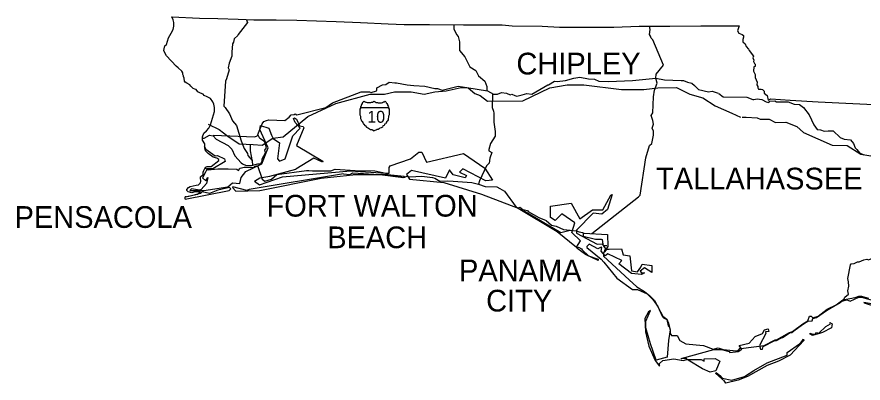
# Model space of a CAD drawing. Extents: x -820.2 to -798.1, y -2199.1 to -2182.2.
# Drawn here: x -808.86 to -807.105, y -2183.81 to -2183.051 of the extents above; entities that cross this region are included whole.
import ezdxf

# ---------------------------------------------------------------- set-up
doc = ezdxf.new("R2010")
doc.units = 0
for name, color, linetype in [('FLMap1', 7, 'Continuous'), ('FLMap2', 7, 'Continuous'), ('FLMap3', 7, 'Continuous'), ('TextMisc', 7, 'Continuous')]:
    doc.layers.add(name, color=color, linetype=linetype)

msp = doc.modelspace()

# ---------------------------------------------------------------- linework, layer by layer
at = {"layer": 'FLMap1'}
msp.add_line((-808.1473, -2183.2389), (-808.0888, -2183.2389), dxfattribs=at)
for points in [[(-808.119, -2183.226), (-808.12, -2183.227), (-808.121, -2183.227), (-808.1225, -2183.2285), (-808.1235, -2183.2285), (-808.125, -2183.2285), (-808.126, -2183.2295), (-808.127, -2183.2295), (-808.1285, -2183.2295), (-808.1295, -2183.2295), (-808.1319, -2183.2295), (-808.1329, -2183.2295), (-808.1344, -2183.2285), (-808.1354, -2183.2285), (-808.1379, -2183.227), (-808.1389, -2183.227), (-808.1404, -2183.226), (-808.1414, -2183.227), (-808.1424, -2183.2285), (-808.1439, -2183.2295), (-808.1439, -2183.2309), (-808.1448, -2183.2329), (-808.1458, -2183.2344), (-808.1458, -2183.2364), (-808.1473, -2183.2379), (-808.1473, -2183.2404), (-808.1483, -2183.2423), (-808.1483, -2183.2448), (-808.1483, -2183.2473), (-808.1483, -2183.2498), (-808.1483, -2183.2518), (-808.1483, -2183.2543), (-808.1473, -2183.2567), (-808.1473, -2183.2592), (-808.1473, -2183.2617), (-808.1458, -2183.2642), (-808.1448, -2183.2667), (-808.1439, -2183.2677), (-808.1424, -2183.2701), (-808.1414, -2183.2726), (-808.1404, -2183.2736), (-808.1379, -2183.2761), (-808.1364, -2183.2771), (-808.1344, -2183.2796), (-808.1319, -2183.281), (-808.1305, -2183.282), (-808.1285, -2183.283), (-808.126, -2183.2845), (-808.1235, -2183.2845), (-808.1225, -2183.2855), (-808.119, -2183.287)], [(-808.119, -2183.226), (-808.1176, -2183.227), (-808.1166, -2183.227), (-808.1156, -2183.2285), (-808.1141, -2183.2285), (-808.1116, -2183.2285), (-808.1106, -2183.2295), (-808.1096, -2183.2295), (-808.1081, -2183.2295), (-808.1071, -2183.2295), (-808.1052, -2183.2295), (-808.1032, -2183.2295), (-808.1017, -2183.2285), (-808.1007, -2183.2285), (-808.0997, -2183.227), (-808.0972, -2183.227), (-808.0957, -2183.226), (-808.0947, -2183.227), (-808.0937, -2183.2285), (-808.0937, -2183.2295), (-808.0923, -2183.2309), (-808.0913, -2183.2329), (-808.0913, -2183.2344), (-808.0898, -2183.2364), (-808.0888, -2183.2379), (-808.0888, -2183.2404), (-808.0878, -2183.2423), (-808.0878, -2183.2448), (-808.0878, -2183.2473), (-808.0878, -2183.2498), (-808.0878, -2183.2518), (-808.0878, -2183.2543), (-808.0888, -2183.2567), (-808.0888, -2183.2592), (-808.0898, -2183.2617), (-808.0898, -2183.2642), (-808.0913, -2183.2667), (-808.0923, -2183.2677), (-808.0937, -2183.2701), (-808.0947, -2183.2726), (-808.0972, -2183.2736), (-808.0982, -2183.2761), (-808.1007, -2183.2771), (-808.1017, -2183.2796), (-808.1042, -2183.281), (-808.1071, -2183.282), (-808.1081, -2183.283), (-808.1106, -2183.2845), (-808.1131, -2183.2845), (-808.1141, -2183.2855), (-808.119, -2183.287)]]:
    msp.add_lwpolyline(points, dxfattribs=at)
at = {"layer": 'FLMap2'}
for points in [[(-808.5105, -2183.4289), (-808.5105, -2183.4244), (-808.5011, -2183.4219), (-808.4951, -2183.4205), (-808.4852, -2183.4185), (-808.4817, -2183.416), (-808.4792, -2183.4135), (-808.4906, -2183.4135), (-808.4966, -2183.416), (-808.5045, -2183.4135), (-808.507, -2183.411), (-808.507, -2183.409), (-808.5035, -2183.4046), (-808.5001, -2183.4026), (-808.4877, -2183.4001), (-808.4832, -2183.3991), (-808.4792, -2183.3952), (-808.4782, -2183.3917), (-808.4792, -2183.3847), (-808.4792, -2183.3823), (-808.4733, -2183.3778), (-808.4733, -2183.3728), (-808.4723, -2183.3694), (-808.4688, -2183.3624), (-808.4653, -2183.3609), (-808.4619, -2183.3609), (-808.4569, -2183.3609), (-808.441, -2183.3485), (-808.441, -2183.3465), (-808.445, -2183.3441), (-808.4524, -2183.3416), (-808.4629, -2183.3346), (-808.4688, -2183.3287), (-808.4698, -2183.3227), (-808.4698, -2183.3178), (-808.4698, -2183.3143), (-808.4748, -2183.3068), (-808.4748, -2183.2999), (-808.4723, -2183.2925), (-808.4663, -2183.287), (-808.4619, -2183.282), (-808.4584, -2183.2751), (-808.45, -2183.2473), (-808.45, -2183.2389), (-808.451, -2183.2319), (-808.4534, -2183.227), (-808.4584, -2183.22), (-808.4653, -2183.2166), (-808.4713, -2183.2141), (-808.4733, -2183.2111), (-808.4792, -2183.2091), (-808.4842, -2183.2066), (-808.4877, -2183.2017), (-808.4906, -2183.2007), (-808.4941, -2183.1997), (-808.4991, -2183.1947), (-808.5011, -2183.1922), (-808.507, -2183.1888), (-808.5105, -2183.1863), (-808.512, -2183.1843), (-808.513, -2183.1783), (-808.5145, -2183.1749), (-808.5145, -2183.1734), (-808.5155, -2183.1709), (-808.5155, -2183.1674), (-808.5179, -2183.1635), (-808.5249, -2183.1565), (-808.5293, -2183.153), (-808.5492, -2183.1317), (-808.5527, -2183.1258), (-808.5551, -2183.1208), (-808.5537, -2183.1143), (-808.5527, -2183.1109), (-808.5492, -2183.1084), (-808.5452, -2183.0945), (-808.5398, -2183.0851), (-808.5353, -2183.0776), (-808.5343, -2183.0707), (-808.5343, -2183.0632), (-808.5353, -2183.0573), (-808.5383, -2183.0513)], [(-808.384, -2183.0563), (-808.3815, -2183.0632), (-808.4008, -2183.0876), (-808.4018, -2183.0895), (-808.4093, -2183.097), (-808.4103, -2183.1039), (-808.4128, -2183.1074), (-808.4137, -2183.1243), (-808.4137, -2183.1292), (-808.4137, -2183.1327), (-808.4197, -2183.1471), (-808.4212, -2183.1565), (-808.4197, -2183.161), (-808.4247, -2183.1793), (-808.4271, -2183.1843), (-808.4306, -2183.2364), (-808.4281, -2183.2389), (-808.4187, -2183.2518), (-808.4128, -2183.2667), (-808.4043, -2183.2761), (-808.3949, -2183.3078), (-808.3884, -2183.3237), (-808.3815, -2183.3346), (-808.3805, -2183.3381), (-808.3721, -2183.3485), (-808.3711, -2183.3589)], [(-807.9538, -2183.0677), (-807.9538, -2183.0757), (-807.9479, -2183.0876), (-807.9444, -2183.092), (-807.9419, -2183.1029), (-807.9419, -2183.1208), (-807.931, -2183.1337), (-807.9206, -2183.155), (-807.9082, -2183.1625), (-807.9022, -2183.1734), (-807.8893, -2183.1843), (-807.8849, -2183.1957), (-807.8849, -2183.2041)], [(-807.6671, -2183.5003), (-807.5703, -2183.4244), (-807.5669, -2183.4205), (-807.555, -2183.3431), (-807.5475, -2183.3178), (-807.543, -2183.3133), (-807.5396, -2183.2964), (-807.5396, -2183.288), (-807.5421, -2183.282), (-807.5396, -2183.2736), (-807.5406, -2183.2657), (-807.544, -2183.2557), (-807.5406, -2183.2498), (-807.5396, -2183.2166), (-807.5371, -2183.2032), (-807.5321, -2183.1888), (-807.5346, -2183.1783), (-807.5336, -2183.1699), (-807.5187, -2183.1516), (-807.5406, -2183.099), (-807.544, -2183.0955), (-807.5455, -2183.091), (-807.5475, -2183.0876), (-807.5465, -2183.0776), (-807.5475, -2183.0697)], [(-808.0362, -2183.1937), (-808.0139, -2183.1947), (-807.993, -2183.1997), (-807.9876, -2183.1997), (-807.9777, -2183.2032), (-807.9444, -2183.1947), (-807.9266, -2183.1972), (-807.8834, -2183.2041), (-807.8715, -2183.2111), (-807.863, -2183.2111), (-807.8546, -2183.2076), (-807.8442, -2183.2091), (-807.8368, -2183.2126), (-807.8333, -2183.2111), (-807.8273, -2183.2141), (-807.8229, -2183.2156), (-807.8174, -2183.2141), (-807.8115, -2183.2126), (-807.802, -2183.2101), (-807.7916, -2183.2111), (-807.7589, -2183.1922), (-807.7569, -2183.1922), (-807.745, -2183.1843), (-807.739, -2183.1853), (-807.7221, -2183.1828), (-807.7043, -2183.1783), (-807.6924, -2183.1759), (-807.6745, -2183.1793), (-807.6621, -2183.1803), (-807.6527, -2183.1843), (-807.6328, -2183.1853), (-807.5827, -2183.1828), (-807.5346, -2183.1783), (-807.5168, -2183.1818), (-807.482, -2183.1828), (-807.4771, -2183.1828), (-807.4686, -2183.1863), (-807.4602, -2183.1888), (-807.4547, -2183.1937), (-807.4463, -2183.2017), (-807.4255, -2183.2066), (-807.4175, -2183.2051), (-807.4056, -2183.2091)], [(-808.4758, -2183.3024), (-808.4713, -2183.3024), (-808.4604, -2183.2964), (-808.4524, -2183.2974), (-808.4465, -2183.3044), (-808.4212, -2183.3178), (-808.4137, -2183.3252), (-808.4078, -2183.3391), (-808.3949, -2183.3535), (-808.3919, -2183.356), (-808.384, -2183.3589), (-808.3731, -2183.3589), (-808.3602, -2183.356), (-808.3542, -2183.356), (-808.3532, -2183.3545), (-808.3507, -2183.351), (-808.3507, -2183.345), (-808.3507, -2183.345), (-808.3443, -2183.3331), (-808.3453, -2183.3277), (-808.3443, -2183.3252), (-808.3418, -2183.3227), (-808.3453, -2183.3108), (-808.3483, -2183.3078), (-808.3557, -2183.3034), (-808.3602, -2183.2949), (-808.3507, -2183.2726), (-808.3473, -2183.2677), (-808.3418, -2183.2657), (-808.3373, -2183.2642), (-808.3041, -2183.2657), (-808.2952, -2183.2592), (-808.2907, -2183.2543), (-808.2848, -2183.2533), (-808.2823, -2183.2518), (-808.2788, -2183.2543), (-808.2193, -2183.2389), (-808.2049, -2183.2295), (-808.1458, -2183.2066), (-808.1285, -2183.2066), (-808.125, -2183.2076), (-808.1141, -2183.2041), (-808.1131, -2183.2032), (-808.1131, -2183.1982), (-808.1017, -2183.1922), (-808.0947, -2183.1912), (-808.0878, -2183.1863), (-808.0759, -2183.1878), (-808.0724, -2183.1878), (-808.0506, -2183.1922), (-808.0362, -2183.1937)], [(-807.873, -2183.2111), (-807.874, -2183.2389), (-807.8715, -2183.2463), (-807.8705, -2183.2508), (-807.8705, -2183.2691), (-807.868, -2183.289), (-807.868, -2183.2984), (-807.8774, -2183.3133), (-807.8809, -2183.3262), (-807.8809, -2183.3287), (-807.875, -2183.3321), (-807.8789, -2183.3441), (-807.8799, -2183.3545), (-807.8859, -2183.3599), (-807.9003, -2183.3907), (-807.9022, -2183.3976)], [(-807.4041, -2183.2101), (-807.3947, -2183.2166), (-807.3461, -2183.2175), (-807.3337, -2183.2225), (-807.3312, -2183.2225), (-807.3243, -2183.221), (-807.3148, -2183.2225), (-807.3054, -2183.227), (-807.3004, -2183.2285), (-807.298, -2183.226), (-807.288, -2183.225), (-807.2846, -2183.227), (-807.2727, -2183.227), (-807.2598, -2183.227), (-807.2479, -2183.2319), (-807.2369, -2183.2329), (-807.2285, -2183.2389), (-807.2166, -2183.2543), (-807.2072, -2183.2751), (-807.2002, -2183.2845), (-807.1928, -2183.2855), (-807.1853, -2183.288), (-807.1774, -2183.287), (-807.1665, -2183.287), (-807.1526, -2183.3009), (-807.1437, -2183.3044), (-807.1308, -2183.3059), (-807.1248, -2183.3133), (-807.1213, -2183.3227), (-807.1179, -2183.3262), (-807.1119, -2183.3331), (-807.1035, -2183.3371)], [(-808.3031, -2183.345), (-808.2872, -2183.2974), (-808.2719, -2183.282), (-808.2823, -2183.2701), (-808.2857, -2183.2617), (-808.2838, -2183.2602), (-808.2798, -2183.2632), (-808.2738, -2183.2771), (-808.2659, -2183.2786), (-808.2644, -2183.281), (-808.2798, -2183.3178)], [(-808.3517, -2183.356), (-808.3383, -2183.3227), (-808.3557, -2183.2845), (-808.3542, -2183.2761), (-808.3373, -2183.282), (-808.3314, -2183.2964), (-808.3279, -2183.3034), (-808.315, -2183.3123), (-808.3195, -2183.345), (-808.315, -2183.35), (-808.3031, -2183.345)], [(-808.4524, -2183.2964), (-808.3661, -2183.2999), (-808.3612, -2183.2974), (-808.3602, -2183.2964)], [(-808.4713, -2183.3192), (-808.4678, -2183.3252), (-808.4485, -2183.3391), (-808.444, -2183.3381), (-808.4291, -2183.345), (-808.4281, -2183.351), (-808.4534, -2183.3659), (-808.4653, -2183.3659), (-808.4688, -2183.3728), (-808.4748, -2183.3847), (-808.4678, -2183.3907), (-808.4639, -2183.3837), (-808.4663, -2183.3966), (-808.4772, -2183.409), (-808.4807, -2183.41), (-808.4976, -2183.4076), (-808.5011, -2183.411), (-808.4723, -2183.411), (-808.4222, -2183.4036), (-808.4128, -2183.3952), (-808.3974, -2183.3966), (-808.3949, -2183.3837), (-808.385, -2183.3718), (-808.3517, -2183.356)], [(-808.2798, -2183.3178), (-808.2252, -2183.35), (-808.2262, -2183.3525), (-808.2441, -2183.3441), (-808.2813, -2183.3669)], [(-808.1677, -2183.3703), (-808.0947, -2183.3753), (-808.0878, -2183.3753), (-808.0878, -2183.3634), (-808.0853, -2183.3599), (-808.0436, -2183.345), (-808.0258, -2183.3312), (-808.0198, -2183.3312), (-808.0104, -2183.3525), (-807.9335, -2183.3346), (-807.8893, -2183.3644), (-807.873, -2183.3892), (-807.8869, -2183.3907), (-807.935, -2183.3659), (-807.9419, -2183.3728), (-807.9275, -2183.3798), (-807.93, -2183.3847), (-807.9548, -2183.3788), (-807.9623, -2183.3684), (-807.9707, -2183.3857), (-808.0412, -2183.3694), (-808.0516, -2183.3778), (-808.0456, -2183.3872), (-807.9742, -2183.3942), (-807.8963, -2183.4185)], [(-808.4698, -2183.3634), (-808.4629, -2183.3684), (-808.45, -2183.3669), (-808.443, -2183.3659), (-808.4212, -2183.3659), (-808.4033, -2183.3669), (-808.3999, -2183.3694), (-808.3974, -2183.3644), (-808.3964, -2183.3644), (-808.3884, -2183.3624), (-808.385, -2183.3624), (-808.3746, -2183.3634), (-808.3671, -2183.3624), (-808.3671, -2183.3609), (-808.3626, -2183.3599), (-808.3602, -2183.3609), (-808.3602, -2183.3609), (-808.3517, -2183.3857), (-808.3507, -2183.3872), (-808.3453, -2183.3917), (-808.3314, -2183.3872), (-808.3205, -2183.3778), (-808.259, -2183.3694), (-808.254, -2183.3694), (-808.2466, -2183.3703), (-808.2084, -2183.3703), (-808.1999, -2183.3669), (-808.1582, -2183.3694), (-808.1176, -2183.3703), (-808.0947, -2183.3753), (-808.0898, -2183.3788), (-808.0699, -2183.3813), (-808.059, -2183.3837), (-808.0506, -2183.3813), (-808.0446, -2183.3823), (-808.0198, -2183.3813), (-807.998, -2183.3837), (-807.993, -2183.3857), (-807.9826, -2183.3917)], [(-808.3671, -2183.3917), (-808.3557, -2183.3847), (-808.3349, -2183.3813), (-808.2813, -2183.3669)], [(-808.3567, -2183.3991), (-808.3091, -2183.3823), (-808.1677, -2183.3703)], [(-808.1821, -2183.3763), (-808.1692, -2183.3778), (-808.1632, -2183.3743), (-808.1081, -2183.3778), (-808.0913, -2183.3778), (-808.0565, -2183.3813), (-808.055, -2183.3837), (-808.058, -2183.3847), (-808.1071, -2183.3788), (-808.1632, -2183.3788)], [(-808.1821, -2183.3763), (-808.378, -2183.409), (-808.3825, -2183.411), (-808.4118, -2183.4036), (-808.4128, -2183.4046), (-808.4058, -2183.4125), (-808.3557, -2183.411), (-808.2287, -2183.3857), (-808.1632, -2183.3788)], [(-808.3671, -2183.3917), (-808.3567, -2183.3991)], [(-807.9826, -2183.3917), (-807.9662, -2183.3907), (-807.9548, -2183.3917), (-807.9161, -2183.3942), (-807.9022, -2183.3976), (-807.8884, -2183.4026), (-807.864, -2183.4036), (-807.8581, -2183.4066), (-807.8487, -2183.4125), (-807.8239, -2183.4458), (-807.8204, -2183.4468), (-807.8164, -2183.4458), (-807.8105, -2183.4502), (-807.801, -2183.4527), (-807.7995, -2183.4542), (-807.7772, -2183.4671), (-807.7623, -2183.473), (-807.7509, -2183.4825), (-807.7415, -2183.485), (-807.7261, -2183.4919), (-807.7122, -2183.4934), (-807.6993, -2183.4944), (-807.6934, -2183.4969), (-807.6864, -2183.4979), (-807.6839, -2183.4993), (-807.6348, -2183.5023), (-807.6338, -2183.5271), (-807.6433, -2183.54), (-807.6433, -2183.547), (-807.5897, -2183.5961)], [(-808.5105, -2183.4289), (-808.4197, -2183.411), (-808.4162, -2183.4076), (-808.4187, -2183.4046), (-808.443, -2183.41), (-808.4604, -2183.417), (-808.4758, -2183.4135), (-808.4792, -2183.417), (-808.506, -2183.4244)], [(-808.5085, -2183.4244), (-808.5105, -2183.4244)], [(-807.8963, -2183.4185), (-807.8204, -2183.4477), (-807.739, -2183.4959), (-807.6993, -2183.5281), (-807.6909, -2183.5152), (-807.7088, -2183.4979), (-807.7028, -2183.478), (-807.7296, -2183.4592), (-807.7435, -2183.473), (-807.7529, -2183.4671), (-807.7529, -2183.4433), (-807.7102, -2183.4373), (-807.6924, -2183.4696), (-807.6656, -2183.4512), (-807.6448, -2183.4512), (-807.6279, -2183.4205), (-807.6249, -2183.4195), (-807.6348, -2183.4502), (-807.6467, -2183.4601), (-807.6646, -2183.4577), (-807.6993, -2183.4934), (-807.6993, -2183.4993), (-807.6562, -2183.5222)], [(-807.809, -2183.4527), (-807.7316, -2183.4979), (-807.7122, -2183.4934)], [(-807.6854, -2183.4993), (-807.6854, -2183.5058), (-807.6596, -2183.5117), (-807.6482, -2183.5117), (-807.6457, -2183.5127), (-807.6448, -2183.5222), (-807.6433, -2183.5246), (-807.6363, -2183.5246)], [(-807.6983, -2183.5306), (-807.6949, -2183.5281), (-807.6889, -2183.5316), (-807.6874, -2183.5341)], [(-807.6874, -2183.5341), (-807.6745, -2183.546), (-807.6542, -2183.5534), (-807.6542, -2183.5559), (-807.6542, -2183.5559), (-807.6805, -2183.5435), (-807.6983, -2183.5306)], [(-807.6061, -2183.5316), (-807.6026, -2183.5445), (-807.5887, -2183.546), (-807.5847, -2183.5772), (-807.5728, -2183.5792), (-807.5654, -2183.5698), (-807.5629, -2183.5638), (-807.543, -2183.5663), (-807.543, -2183.5807), (-807.5584, -2183.5713), (-807.5669, -2183.5782), (-807.5644, -2183.5817), (-807.5584, -2183.5817), (-807.5644, -2183.5852), (-807.5847, -2183.5832), (-807.611, -2183.5628), (-807.6051, -2183.5559), (-807.6338, -2183.5425), (-807.6398, -2183.546), (-807.6482, -2183.5366), (-807.6467, -2183.5291), (-807.6482, -2183.5281), (-807.6552, -2183.5316), (-807.673, -2183.5222), (-807.678, -2183.5271), (-807.678, -2183.5291), (-807.6482, -2183.5534), (-807.6423, -2183.5594), (-807.6155, -2183.5926), (-807.5827, -2183.6164), (-807.5728, -2183.6164), (-807.5525, -2183.6249), (-807.5406, -2183.6368)], [(-807.6562, -2183.5222), (-807.6457, -2183.5212), (-807.6423, -2183.5271), (-807.6388, -2183.5316), (-807.6408, -2183.5351), (-807.6408, -2183.5366), (-807.6398, -2183.5375), (-807.6363, -2183.5326), (-807.6314, -2183.5326)], [(-807.6314, -2183.5326), (-807.6061, -2183.5316)], [(-807.1447, -2183.6368), (-807.1427, -2183.6318), (-807.1352, -2183.6259), (-807.1367, -2183.6189), (-807.1342, -2183.6095), (-807.1352, -2183.6001), (-807.1367, -2183.5936), (-807.1308, -2183.5653), (-807.1293, -2183.5628), (-807.1233, -2183.5619), (-807.1164, -2183.5584), (-807.1129, -2183.5584), (-807.1035, -2183.5544), (-807.097, -2183.5534), (-807.0936, -2183.5544), (-807.0851, -2183.5509)], [(-807.5897, -2183.5961), (-807.5738, -2183.6105), (-807.5584, -2183.6199), (-807.5475, -2183.6283), (-807.5371, -2183.6392), (-807.5247, -2183.6621), (-807.5202, -2183.6715), (-807.5118, -2183.6775), (-807.5083, -2183.6859), (-807.5048, -2183.7003), (-807.5048, -2183.7072), (-807.5024, -2183.7112), (-807.4905, -2183.7112), (-807.4845, -2183.7216), (-807.4721, -2183.7286), (-807.4508, -2183.731), (-807.4354, -2183.732), (-807.416, -2183.7395), (-807.4056, -2183.737), (-807.3947, -2183.7405), (-807.3674, -2183.7434), (-807.3635, -2183.7424), (-807.359, -2183.737), (-807.358, -2183.738), (-807.3099, -2183.732), (-807.3099, -2183.732), (-807.287, -2183.7206), (-807.2846, -2183.7206), (-807.2573, -2183.7052), (-807.2513, -2183.7028), (-807.23, -2183.6869), (-807.2191, -2183.6809), (-807.2156, -2183.6715), (-807.2121, -2183.6715), (-807.2087, -2183.675), (-807.1977, -2183.6715), (-807.1794, -2183.6571), (-807.1605, -2183.6477), (-807.1466, -2183.6378), (-807.1437, -2183.6368), (-807.1283, -2183.6343), (-807.1189, -2183.6318), (-807.1139, -2183.6298), (-807.1079, -2183.6298), (-807.0936, -2183.6343)], [(-807.5406, -2183.6368), (-807.5301, -2183.6512), (-807.5212, -2183.6715), (-807.5187, -2183.675), (-807.5118, -2183.6784), (-807.5093, -2183.6913), (-807.5068, -2183.6928), (-807.5048, -2183.6993), (-807.5083, -2183.7216), (-807.5108, -2183.7563), (-807.5336, -2183.7623), (-807.5455, -2183.7286), (-807.555, -2183.6958), (-807.555, -2183.6819), (-807.5455, -2183.6596), (-807.55, -2183.6621), (-807.5574, -2183.676), (-807.5559, -2183.7037), (-807.549, -2183.7335), (-807.5361, -2183.7633), (-807.5272, -2183.7752), (-807.5272, -2183.7707), (-807.5272, -2183.7692), (-807.5202, -2183.7633), (-807.4974, -2183.7598), (-807.4781, -2183.7633), (-807.4701, -2183.7613), (-807.4701, -2183.7588), (-807.4805, -2183.7598), (-807.482, -2183.7588), (-807.4141, -2183.7405), (-807.3987, -2183.7405), (-807.3828, -2183.7444), (-807.3813, -2183.7469), (-807.3635, -2183.7444), (-807.3565, -2183.7395), (-807.3615, -2183.732), (-807.3411, -2183.7276), (-807.3287, -2183.7132), (-807.3133, -2183.7072), (-807.3089, -2183.6993), (-807.3019, -2183.6978), (-807.3004, -2183.7028), (-807.3074, -2183.7037), (-807.3064, -2183.7072), (-807.3193, -2183.732), (-807.3173, -2183.7395), (-807.3133, -2183.7395), (-807.3123, -2183.7345), (-807.288, -2183.7216)], [(-807.1809, -2183.6596), (-807.1739, -2183.6551), (-807.1526, -2183.6427), (-807.1486, -2183.6402), (-807.1387, -2183.6378), (-807.1342, -2183.6392)], [(-807.1387, -2183.6378), (-807.1318, -2183.6402), (-807.1318, -2183.6402), (-807.1139, -2183.6318), (-807.1079, -2183.6318), (-807.0782, -2183.6402), (-807.0767, -2183.6392), (-807.0712, -2183.6457), (-807.0757, -2183.6477), (-807.1035, -2183.6427), (-807.1025, -2183.6437), (-807.0792, -2183.6512)], [(-807.288, -2183.7216), (-807.2846, -2183.7216), (-807.2751, -2183.7166), (-807.2717, -2183.7157), (-807.2563, -2183.7052), (-807.2528, -2183.7052), (-807.2459, -2183.6993), (-807.2285, -2183.6869), (-807.2191, -2183.6819), (-807.2106, -2183.6809), (-807.2087, -2183.676), (-807.2012, -2183.674), (-807.1809, -2183.6596)], [(-807.2146, -2183.7087), (-807.2146, -2183.7062), (-807.2097, -2183.7087), (-807.2037, -2183.7087), (-807.2012, -2183.7052), (-807.1968, -2183.7062), (-807.1819, -2183.6928), (-807.1724, -2183.6869), (-807.1739, -2183.6844), (-807.169, -2183.6869), (-807.17, -2183.6958)], [(-807.17, -2183.6958), (-807.1888, -2183.7052), (-807.1928, -2183.7062), (-807.2097, -2183.7112), (-807.2146, -2183.7087)], [(-807.3912, -2183.8064), (-807.4101, -2183.7901), (-807.4091, -2183.7881), (-807.4021, -2183.7945), (-807.3972, -2183.7995), (-807.3768, -2183.804), (-807.3506, -2183.796), (-807.3312, -2183.7836), (-807.3039, -2183.7682), (-807.2622, -2183.7519), (-807.2622, -2183.7469), (-807.2369, -2183.7286), (-807.231, -2183.7226), (-807.2285, -2183.7191), (-807.2275, -2183.7216), (-807.2563, -2183.7519), (-807.2801, -2183.7648), (-807.3039, -2183.7732), (-807.3446, -2183.796), (-807.3635, -2183.804), (-807.3892, -2183.8099), (-807.3937, -2183.804)], [(-807.4686, -2183.7613), (-807.4403, -2183.7613), (-807.4344, -2183.7648), (-807.4344, -2183.7598), (-807.4116, -2183.7588), (-807.4021, -2183.7648), (-807.4101, -2183.7846), (-807.422, -2183.7871), (-807.4379, -2183.7801), (-807.4676, -2183.7623)], [(-807.4676, -2183.7623), (-807.4686, -2183.7613)]]:
    msp.add_lwpolyline(points, dxfattribs=at)
at = {"layer": 'FLMap3'}
for points in [[(-808.5383, -2183.0513), (-808.4807, -2183.0538), (-808.443, -2183.0548), (-808.4008, -2183.0563), (-808.3686, -2183.0573), (-808.322, -2183.0573), (-808.2788, -2183.0583), (-808.1974, -2183.0608), (-808.1473, -2183.0632), (-808.0898, -2183.0657), (-808.0565, -2183.0667), (-808.0039, -2183.0667), (-807.9335, -2183.0677), (-807.8536, -2183.0677), (-807.8323, -2183.0697), (-807.7703, -2183.0707), (-807.7341, -2183.0722), (-807.6854, -2183.0722), (-807.6214, -2183.0722), (-807.5688, -2183.0707), (-807.5058, -2183.0707), (-807.4413, -2183.0697), (-807.3615, -2183.0697), (-807.3649, -2183.0801), (-807.3625, -2183.0851), (-807.3555, -2183.0876), (-807.353, -2183.0895), (-807.353, -2183.093), (-807.354, -2183.098), (-807.354, -2183.1029), (-807.3496, -2183.1074), (-807.3471, -2183.1124), (-807.3426, -2183.1183), (-807.3411, -2183.1208), (-807.3322, -2183.1327), (-807.3337, -2183.1362), (-807.3312, -2183.1411), (-807.3322, -2183.1436), (-807.3302, -2183.1481), (-807.3287, -2183.1491), (-807.3287, -2183.154), (-807.3312, -2183.155), (-807.3322, -2183.1635), (-807.3287, -2183.1709), (-807.3287, -2183.1769), (-807.3243, -2183.1863), (-807.3252, -2183.1922), (-807.3228, -2183.1957), (-807.3228, -2183.1982), (-807.3218, -2183.2007), (-807.3158, -2183.2007), (-807.3133, -2183.2017), (-807.3099, -2183.2051), (-807.3099, -2183.2091), (-807.3039, -2183.2141), (-807.3019, -2183.2235), (-807.296, -2183.221), (-807.2563, -2183.2235), (-807.1977, -2183.227), (-807.1258, -2183.2309), (-807.0534, -2183.2344)], [(-808.4629, -2183.2736), (-808.44, -2183.2845), (-808.4222, -2183.2984), (-808.3984, -2183.3143), (-808.3696, -2183.3158), (-808.3507, -2183.3168), (-808.3289, -2183.3024), (-808.3076, -2183.2999), (-808.2565, -2183.2577), (-808.1984, -2183.2309), (-808.127, -2183.2111), (-808.0972, -2183.2111), (-808.0769, -2183.2066), (-808.0421, -2183.2066), (-808.0149, -2183.2111), (-807.993, -2183.2066), (-807.9697, -2183.2041), (-807.9385, -2183.1972), (-807.9241, -2183.1982), (-807.9097, -2183.2101), (-807.8988, -2183.2141), (-807.8834, -2183.226), (-807.8105, -2183.225), (-807.7544, -2183.1982), (-807.7182, -2183.1922), (-807.6839, -2183.1922), (-807.6061, -2183.2017), (-807.5594, -2183.2017), (-807.5301, -2183.1982), (-807.4915, -2183.1972), (-807.4642, -2183.2111), (-807.4369, -2183.219), (-807.4116, -2183.2354), (-807.3768, -2183.2508), (-807.359, -2183.2592)], [(-807.3555, -2183.2592), (-807.3471, -2183.2592), (-807.3243, -2183.2602), (-807.3183, -2183.2632), (-807.2995, -2183.2632), (-807.2861, -2183.2701), (-807.2647, -2183.2691), (-807.2419, -2183.2786), (-807.2285, -2183.2905), (-807.169, -2183.3168), (-807.1377, -2183.3178), (-807.1094, -2183.3356), (-807.0603, -2183.3441)], [(-808.3711, -2183.351), (-808.3755, -2183.3287), (-808.3755, -2183.3158)]]:
    msp.add_lwpolyline(points, dxfattribs=at)

# ---------------------------------------------------------------- texts
at = {"layer": 'TextMisc'}
for s, height, p in [('CHIPLEY', 0.045, (-807.8237, -2183.1705)), ('10', 0.0247, (-808.1329, -2183.2706)), ('TALLAHASSEE', 0.045, (-807.534, -2183.4088)), ('FORT WALTON', 0.045, (-808.342, -2183.465)), ('PENSACOLA', 0.045, (-808.8646, -2183.4884)), ('BEACH', 0.045, (-808.2162, -2183.5305)), ('PANAMA', 0.045, (-807.9427, -2183.599)), ('CITY', 0.045, (-807.8865, -2183.6617))]:
    msp.add_text(s, height=height, dxfattribs=at).set_placement(p)

doc.saveas('drawing.dxf')
